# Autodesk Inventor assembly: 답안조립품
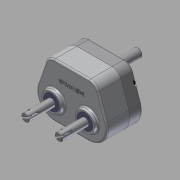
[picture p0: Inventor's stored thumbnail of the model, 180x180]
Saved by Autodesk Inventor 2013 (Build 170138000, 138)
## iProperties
Created: 2014-12
Part Number: 답안조립품
Document SubType Name: Assembly
Designer: Administrator
Author: Administrator
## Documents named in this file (14)
- C:\Users\Administrator\Desktop\441209V1003\답안조립품.iam
- C:\Users\Administrator\Desktop\441209V1003\본체.ipt
- C:\Users\Administrator\Desktop\441209V1003\오일시일-D-15.ipt
- C:\Users\Administrator\Desktop\441209V1003\베어링- 6203.ipt
- C:\Users\Administrator\Desktop\441209V1003\커버.ipt
- C:\Users\Administrator\Desktop\441209V1003\M 5 x 35.ipt
- C:\Users\Administrator\Desktop\441209V1003\베어링- 6202.ipt
- C:\Users\Administrator\Desktop\441209V1003\메인축.ipt
- C:\Users\Administrator\Desktop\441209V1003\멈춤링.ipt
- C:\Users\Administrator\Desktop\441209V1003\서브축.ipt
- C:\Users\Administrator\Desktop\441209V1003\메인기어.ipt
- C:\Users\Administrator\Desktop\441209V1003\키5x5.ipt
- C:\Users\Administrator\Desktop\441209V1003\서브기어.ipt
- C:\Users\Administrator\Desktop\441209V1003\오일시일-D-17.ipt
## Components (15 placed, 6 different names)
1. KS B 2804 D D - 15 30 7:1
2. KS B 2804 D D - 15 30 7:2
3. KS B 2023 6203 - 17 x 40 x 12:1 — 각도:1
4. KS B 1003 - 미터 M 5 x 35:1
5. KS B 1003 - 미터 M 5 x 35:2
6. KS B 1003 - 미터 M 5 x 35:3
7. KS B 2023 6203 - 17 x 40 x 12:2 — 각도:3
8. KS B 2023 6203 - 17 x 40 x 12:3 — 각도:2
9. KS B 2023 6203 - 17 x 40 x 12:4 — 각도:5
10. KS B 2023 6202 - 15 x 35 x 11:1 — 각도:4
11. KS B 2023 6202 - 15 x 35 x 11:2 — 각도:6
12. KS B 1336 17 x 1:1
13. KS B 1336 17 x 1:2
14. KS B 1336 17 x 1:3
15. KS B 2804 D D - 17 30 8:1
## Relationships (6: Angle 6)
- 각도:1 [Angle]: KS B 2023 6203 - 17 x 40 x 12:1
- 각도:2 [Angle]: KS B 2023 6203 - 17 x 40 x 12:3
- 각도:3 [Angle]: KS B 2023 6203 - 17 x 40 x 12:2
- 각도:4 [Angle]: KS B 2023 6202 - 15 x 35 x 11:1
- 각도:5 [Angle]: KS B 2023 6203 - 17 x 40 x 12:4
- 각도:6 [Angle]: KS B 2023 6202 - 15 x 35 x 11:2
